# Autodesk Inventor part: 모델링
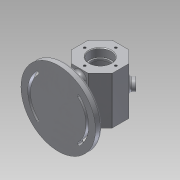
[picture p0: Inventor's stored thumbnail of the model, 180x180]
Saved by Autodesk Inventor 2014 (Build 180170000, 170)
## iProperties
Created: 2017-06
Part Number: 모델링
Material: Aluminum 6061
Document SubType Name: Modeling
Designer: user
Density: 2.71 g/cm^3
Appearance: Aluminum - Flat
Author: user
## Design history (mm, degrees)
sketch "Sketch2"
  geometry: C1 r 55 at (0, 0); 1 further point
  constraints: 1 centre point, 1 coincident
extrude "Extrusion1" new body sketch "Sketch2" distance "d0" = 10; taper "d1" = 0 deg
sketch "Sketch3"
  geometry: L1 (-55, 0)-(-55, 10) reference; L2 (-55, 10)-(55, 10) reference; L3 (55, 10)-(55, 0) reference; L4 (55, 0)-(-55, 0) reference; L5 (0, 0)-(0, 62); L6 (12.426, 92)-(30, 74.426); L7 (30, 74.426)-(30, 49.574); L8 (30, 49.574)-(12.426, 32); L9 (12.426, 32)-(-12.426, 32); L10 (-12.426, 32)-(-30, 49.574); L11 (-30, 49.574)-(-30, 74.426); L12 (-30, 74.426)-(-12.426, 92); L13 (-12.426, 92)-(12.426, 92); 2 further points
  constraints: 18 end point, 1 midpoint, 17 other
extrude "Extrusion2" join sketch "Sketch3" stored distance "d2" = 70; taper "d3" = 0 deg
sketch "Sketch4"
  geometry: L1 (0, 55)-(10, 55) reference; L2 (10, 55)-(10, -55) reference; L3 (10, -55)-(0, -55) reference; L4 (0, -55)-(0, 55) reference; L5 (92, -35)-(32, -35) reference; L6 (32, -35)-(32, 35) reference; L7 (32, 35)-(92, 35) reference; L8 (92, 35)-(92, -35) reference; L9 (62, 35)-(62, -35); L10 (62, 35)-(78, 35); L11 (78, 35)-(78, 23.3); L12 (76, 23)-(76, 20); L13 (87, 17)-(87, -17); L14 (84, -20)-(76, -20); L15 (76, -20)-(76, -23); L16 (76, -23)-(77.7, -23); L17 (78, -23.3)-(78, -35); L18 (77.7, 23)-(76, 23); L19 (84, 20)-(76, 20); L20 (78, -35)-(62, -35); L21 (62, 35)-(62, -35); A1 r 0.3 centre (77.7, 23.3) between (77.7, 23) and (78, 23.3); A2 r 0.3 centre (77.7, -23.3) between (78, -23.3) and (77.7, -23); A3 r 3 centre (84, 17) between (87, 17) and (84, 20); A4 r 3 centre (84, -17) between (84, -20) and (87, -17); 1 further point
  constraints: 26 end point, 8 point on circle, 8 tangent, 4 centre point, 2 equal radius, 2 midpoint, 2 point on line
  dimensions: "d4" = 0.3 radius of A1; "d5" = 3 radius of A3
revolve "Revolution1" sketch "Sketch4" stored, may be unused: angle "d6" = 90 deg
sketch "Sketch6"
  geometry: L1 (0, 0)-(55, 0.071); L2 (0, 0)-(26.836, 26.905); L3 (33.898, 33.985)-(44.934, 45.049); L4 (26.905, -26.836)-(0, 0); L5 (0, 0)-(26.905, -26.836); L6 (33.985, -33.898)-(47.581, -47.459); L7 (47.581, -47.459)-(33.985, -33.898); L8 (-38.83, -38.952)-(-48.246, -48.396); L9 (0, 0)-(-26.828, -26.912); L10 (0, 0)-(-38, -0.059); L11 (0, 0)-(-26.912, 26.828); A1 r 55 centre (0, 0) between (55, 0.071) and (-38.83, -38.952) reference; A2 r 2 centre (-30.358, -30.453) between (-31.77, -31.869) and (-28.946, -29.037); A3 r 2 centre (-30.453, 30.358) between (-29.037, 28.946) and (-31.869, 31.77); A4 r 2 centre (30.445, -30.367) between (29.029, -28.954) and (31.861, -31.779); A5 r 2 centre (30.367, 30.445) between (31.779, 31.861) and (28.954, 29.029); A6 r 5 centre (30.367, 30.445) between (33.898, 33.985) and (26.836, 26.905); A7 r 41 centre (0, 0) between (29.029, -28.954) and (28.954, 29.029); A8 r 45 centre (0, 0) between (31.861, -31.779) and (31.779, 31.861); A9 r 5 centre (30.445, -30.367) between (26.905, -26.836) and (33.985, -33.898); A10 r 5 centre (-30.358, -30.453) between (-33.888, -33.994) and (-26.828, -26.912); A11 r 41 centre (0, 0) between (-29.037, 28.946) and (-28.946, -29.037); A12 r 45 centre (0, 0) between (-31.869, 31.77) and (-31.77, -31.869); A13 r 5 centre (-30.453, 30.358) between (-26.912, 26.828) and (-33.994, 33.888); A14 r 38 centre (0, 0) between (-26.912, 26.828) and (-26.828, -26.912); A15 r 38 centre (0, 0) between (26.905, -26.836) and (26.836, 26.905); A16 r 48 centre (0, 0) between (-33.994, 33.888) and (-33.888, -33.994); A17 r 48 centre (0, 0) between (33.985, -33.898) and (33.898, 33.985); 1 further point
  constraints: 35 point on circle, 22 end point, 16 centre point, 9 coincident, 2 other
extrude "Extrusion3" cut sketch "Sketch6" distance "d11" = 3; taper "d12" = 0 deg
sketch "Sketch7"
  geometry: C1 r 55 at (0, 0) reference; A1 r 41 centre (0, 0) between (-29.037, 28.946) and (-28.946, -29.037) reference; A2 r 2 centre (-30.358, -30.453) between (-31.77, -31.869) and (-28.946, -29.037) reference; A3 r 45 centre (0, 0) between (-31.869, 31.77) and (-31.77, -31.869) reference; A4 r 2 centre (-30.453, 30.358) between (-29.037, 28.946) and (-31.869, 31.77) reference; A5 r 5 centre (-30.453, 30.358) between (-26.912, 26.828) and (-33.994, 33.888) reference; A6 r 48 centre (0, 0) between (-33.994, 33.888) and (-33.888, -33.994) reference; A7 r 5 centre (-30.358, -30.453) between (-33.888, -33.994) and (-26.828, -26.912) reference; A8 r 38 centre (0, 0) between (-26.912, 26.828) and (-26.828, -26.912) reference; A9 r 41 centre (0, 0) between (29.029, -28.954) and (28.954, 29.029) reference; A10 r 2 centre (30.367, 30.445) between (31.779, 31.861) and (28.954, 29.029) reference; A11 r 45 centre (0, 0) between (31.861, -31.779) and (31.779, 31.861) reference; A12 r 2 centre (30.445, -30.367) between (29.029, -28.954) and (31.861, -31.779) reference; A13 r 5 centre (30.367, 30.445) between (33.898, 33.985) and (26.836, 26.905) reference; A14 r 38 centre (0, 0) between (26.905, -26.836) and (26.836, 26.905) reference; A15 r 5 centre (30.445, -30.367) between (26.905, -26.836) and (33.985, -33.898) reference; A16 r 48 centre (0, 0) between (33.985, -33.898) and (33.898, 33.985) reference; A17 r 2 centre (-30.358, -30.453) between (-31.77, -31.869) and (-28.946, -29.037); A18 r 2 centre (-30.453, 30.358) between (-29.037, 28.946) and (-31.869, 31.77); A19 r 2 centre (30.367, 30.445) between (31.779, 31.861) and (28.954, 29.029); A20 r 2 centre (30.445, -30.367) between (29.029, -28.954) and (31.861, -31.779); A21 r 45 centre (0, 0) between (31.861, -31.779) and (31.779, 31.861); A22 r 45 centre (0, 0) between (-31.869, 31.77) and (-31.77, -31.869); A23 r 41 centre (0, 0) between (29.029, -28.954) and (28.954, 29.029); A24 r 41 centre (0, 0) between (-29.037, 28.946) and (-28.946, -29.037)
  constraints: 16 point on circle, 8 centre point, 6 coincident
extrude "Extrusion4" cut sketch "Sketch7" stored distance "d13" = 3; taper "d14" = 0 deg
workplane "Work Plane1"
sketch "Sketch8"
  geometry: L1 (8.551, 10.352)-(8.551, 60.127); L2 (8.551, 60.127)-(15.756, 60.127); L3 (15.756, 60.127)-(15.756, 10.352); L4 (15.756, 10.352)-(8.551, 10.352); L5 (24.853, 0)-(0, 0) reference; 2 further points
  constraints: 1 point on line, 2 other
emboss "Emboss1" sketch "Sketch8" dims "d16" = 0.5, "d17" = 0
sketch "Sketch9"
  geometry: L1 (-5, -24)-(-5, 24); L2 (5, 24)-(5, -24); A1 r 5 centre (0, -24) between (-5, -24) and (5, -24); A2 r 5 centre (0, 24) between (5, 24) and (-5, 24)
  constraints: 4 end point, 4 point on circle, 2 centre point
extrude "Extrusion5" join sketch "Sketch9" stored distance "d18" = 3; taper "d19" = 0 deg
fillet "Fillet1" dims "d20" = 5
workplane "Work Plane2"
sketch "Sketch10"
  geometry: L1 (-24.853, 70)-(0, 70) reference; L2 (-12.426, 70)-(-12.426, 35); C1 r 8 at (-12.426, 35); 1 further point
  constraints: 2 end point, 1 centre point, 1 coincident, 1 midpoint
extrude "Extrusion6" join sketch "Sketch10" stored distance "d22" = 3; taper "d23" = 0 deg
sketch "Sketch11"
  geometry: C1 r 8 at (0, 0) reference; 2 further points
  constraints: 1 coincident
hole "Hole1" sketch "Sketch11" at (0, 0) diameter "d24" = 8; stored, may be unused: countersink angle "d28" = 90 deg, drill point angle "d30" = 118 deg; dims "d25" = 6, "d26" = 4, "d27" = 2, "d29" = 30
chamfer "Chamfer1" distance "d31" = 1; stored, may be unused: second distance "d32" = 2, angle "d33" = 45 deg
fillet "Fillet2" dims "d34" = 3
sketch "Sketch12"
  geometry: L1 (-32.438, 7)-(-28.279, 7) reference; L2 (-28.279, 7)-(-28.279, 10) reference; L3 (-28.279, 10)-(28.566, 10) reference; L4 (28.566, 10)-(28.566, 7) reference; L5 (28.566, 7)-(32.324, 7) reference; L6 (32.324, 7)-(32.324, 10) reference; L7 (32.324, 10)-(42.426, 10) reference; L8 (42.426, 10)-(42.426, 0) reference; L9 (42.426, 0)-(-42.426, 0) reference; L10 (-42.426, 0)-(-42.426, 10) reference; L11 (-42.426, 10)-(-32.438, 10) reference; L12 (-32.438, 10)-(-32.438, 7) reference; L13 (-12.426, 32)-(-30, 49.574) reference; L14 (-30, 49.574)-(-30, 74.426) reference; L15 (-30, 74.426)-(-12.426, 92) reference; L16 (-12.426, 92)-(12.426, 92) reference; L17 (12.426, 92)-(30, 74.426) reference; L18 (30, 74.426)-(30, 49.574) reference; L19 (30, 49.574)-(12.426, 32) reference; L20 (12.426, 32)-(-12.426, 32) reference; L21 (0, 85)-(0, 39); L22 (23, 62)-(-23, 62); C1 r 16 at (0, 62) reference; A1 r 23 centre (0, 62) between (0, 85) and (0, 39); 5 further points
  constraints: 5 coincident, 4 end point, 4 point on circle, 1 centre point
hole "Hole2" sketch "Sketch12" at (0, 85), (23, 62), (0, 39), (-23, 62) diameter "d35" = 3.459; stored, may be unused: countersink angle "d39" = 90 deg, drill point angle "d41" = 118 deg; dims "d36" = 8, "d37" = 4, "d38" = 2, "d40" = 10
sketch "Sketch13"
  geometry: L1 (0, 85)-(0, 39); L2 (23, 62)-(-23, 62); C1 r 16 at (0, 62) reference; A1 r 23 centre (0, 62) between (0, 85) and (0, 39); 5 further points
  constraints: 5 coincident, 4 end point, 4 point on circle, 1 centre point
hole "Hole3" sketch "Sketch13" at (-23, 62), (0, 39), (23, 62), (0, 85) diameter "d42" = 3.459; stored, may be unused: countersink angle "d46" = 90 deg, drill point angle "d48" = 118 deg; dims "d43" = 8, "d44" = 4, "d45" = 2, "d47" = 10
chamfer "Chamfer2" distance "d49" = 1; stored, may be unused: second distance "d50" = 2, angle "d51" = 45 deg
fillet "Fillet3" dims "d52" = 3
fillet "Fillet4" dims "d53" = 1
body "Solid1"
node "Project Cut Edges1"
node "Project Cut Edges2"
node "Project Cut Edges3"
node "Project Cut Edges4"
node "Project Cut Edges5"
node "Project Cut Edges6"
other parameters: "d7" = 45 deg, "d8" = 45 deg, "d9" = 45 deg, "d10" = 45 deg, "d21" = 7
